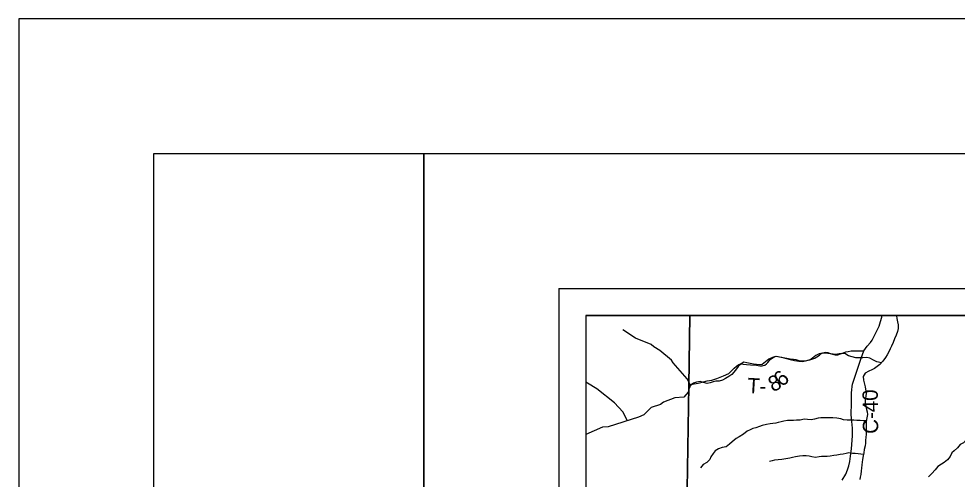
# Model space of a CAD drawing. Extents: x 0 to 34, y 0 to 22.
# Drawn here: x 0 to 3.475, y 20.293 to 22 of the extents above; entities that cross this region are included whole.
import ezdxf

# ---------------------------------------------------------------- set-up
doc = ezdxf.new("R2010")
doc.units = 0
for name, color, linetype in [('Default', 7, 'Continuous'), ('GM_X_County_Road', 7, 'Continuous'), ('GM_X_County_Road_Text', 7, 'Continuous'), ('GM_X_Minor_River', 7, 'Continuous'), ('GM_X_Township_Road', 7, 'Continuous'), ('GM_X_Township_Road_Text', 7, 'Continuous'), ('SH_Border', 7, 'Continuous'), ('SH_Cut_Line', 7, 'Continuous'), ('SH_Data', 7, 'Continuous')]:
    doc.layers.add(name, color=color, linetype=linetype)

msp = doc.modelspace()

# ---------------------------------------------------------------- linework, layer by layer
at = {"layer": 'Default'}
for points in [[(2.4313, 15.0183), (2.4545, 17.2795), (2.4586, 17.7785), (2.4581, 18.1772), (2.4581, 18.1825), (2.4573, 18.9074), (2.4757, 20.2566), (2.4809, 20.6393), (2.4845, 20.9), (2.1, 20.9), (2.1, 14.9328)], [(6.416, 20.9), (2.4845, 20.9), (2.4809, 20.6393), (2.4757, 20.2566), (2.4573, 18.9074), (2.4581, 18.1825), (2.4581, 18.1772), (2.4586, 17.7785), (2.4545, 17.2795), (2.6193, 17.2753), (3.4366, 17.255), (3.467, 17.2465), (3.4629, 17.4891), (3.5442, 17.5398)]]:
    msp.add_lwpolyline(points, dxfattribs=at)
at = {"layer": 'GM_X_County_Road'}
msp.add_lwpolyline([(3.0492, 20.2896), (3.0625, 20.3124), (3.0695, 20.3285), (3.0736, 20.3427), (3.0777, 20.3585), (3.0807, 20.3786), (3.0833, 20.4061), (3.0866, 20.4384), (3.0878, 20.4541), (3.0876, 20.4704), (3.0873, 20.4821), (3.0845, 20.507), (3.083, 20.5332), (3.0833, 20.5754), (3.0835, 20.6131), (3.0845, 20.625), (3.0858, 20.637), (3.0876, 20.6459), (3.0895, 20.6525), (3.1082, 20.7087), (3.1191, 20.742), (3.129, 20.7694), (3.1421, 20.7863), (3.1538, 20.8003), (3.1604, 20.8092), (3.1744, 20.8354), (3.1859, 20.8605), (3.1913, 20.8778), (3.1963, 20.8935), (3.1978, 20.9)], dxfattribs=at)
at = {"layer": 'GM_X_Minor_River'}
for points in [[(3.2506, 20.9), (3.2507, 20.8985), (3.2514, 20.8886), (3.2543, 20.8761), (3.2569, 20.8658), (3.2565, 20.8521), (3.2537, 20.8408), (3.2491, 20.8275), (3.2426, 20.8131), (3.2376, 20.8003), (3.2318, 20.787), (3.2272, 20.7768), (3.2222, 20.7658), (3.2161, 20.7549), (3.2092, 20.7451), (3.1996, 20.7311), (3.1882, 20.7182), (3.1786, 20.7107), (3.1691, 20.7036), (3.1596, 20.6987), (3.1475, 20.6935), (3.1342, 20.6859), (3.1265, 20.6742), (3.1279, 20.6606), (3.132, 20.6457), (3.1346, 20.6362), (3.1357, 20.6267), (3.1375, 20.6134), (3.137, 20.5994), (3.1339, 20.5861), (3.1342, 20.5744), (3.1364, 20.5649), (3.1394, 20.5523), (3.1416, 20.5428), (3.1427, 20.5333), (3.1407, 20.5204), (3.1376, 20.5076), (3.1383, 20.4943), (3.1378, 20.4833), (3.1377, 20.4586), (3.1372, 20.4487), (3.136, 20.437), (3.1352, 20.4268), (3.134, 20.4173), (3.1309, 20.404), (3.1293, 20.3911), (3.1269, 20.3805), (3.1246, 20.3669), (3.123, 20.357)], [(2.4871, 20.6422), (2.4747, 20.6655), (2.4232, 20.7244), (2.4174, 20.7348), (2.3744, 20.7703), (2.352, 20.7845), (2.3424, 20.7927), (2.2839, 20.8161), (2.237, 20.8465)], [(3.1943, 20.7251), (3.178, 20.7289), (3.1652, 20.7343), (3.1519, 20.742), (3.1402, 20.7447), (3.1262, 20.7433), (3.1, 20.7435), (3.0861, 20.747), (3.0724, 20.7505), (3.0585, 20.7589), (3.0475, 20.7597), (3.0376, 20.7575), (3.0247, 20.7561), (3.0077, 20.7577), (2.9963, 20.7593), (2.977, 20.7609), (2.9641, 20.7584), (2.952, 20.752), (2.939, 20.7422), (2.9291, 20.7351), (2.9181, 20.7317), (2.9056, 20.7303), (2.8931, 20.7304), (2.8787, 20.7361), (2.8685, 20.7377), (2.8568, 20.7389), (2.8443, 20.7413), (2.8291, 20.7429), (2.817, 20.746), (2.8038, 20.7484), (2.7913, 20.745), (2.778, 20.7379), (2.7654, 20.7281), (2.7525, 20.7187), (2.7418, 20.7173), (2.732, 20.7181), (2.7214, 20.7193), (2.7082, 20.7228), (2.6957, 20.7248), (2.6851, 20.7267), (2.6748, 20.7215), (2.6638, 20.7109), (2.6542, 20.6981), (2.6401, 20.6815), (2.6294, 20.6743), (2.6173, 20.6664), (2.6066, 20.6608), (2.5933, 20.6567), (2.582, 20.6568), (2.5721, 20.6546), (2.5599, 20.6512), (2.5497, 20.6483), (2.5361, 20.6522), (2.5236, 20.6553), (2.5099, 20.6531), (2.4986, 20.649), (2.4871, 20.6422), (2.4821, 20.6297), (2.4816, 20.6283)], [(2.2537, 20.5099), (2.2371, 20.543), (2.2066, 20.5771), (2.1401, 20.628), (2.1058, 20.6497), (2.1, 20.6528)], [(2.4816, 20.6283), (2.4793, 20.6161), (2.4624, 20.5971), (2.4294, 20.5953), (2.3874, 20.5784), (2.3766, 20.5707), (2.3423, 20.5587), (2.3152, 20.5324), (2.2956, 20.523), (2.1828, 20.4878), (2.1623, 20.486), (2.1, 20.4592)], [(3.1381, 20.5097), (3.127, 20.5103), (3.1164, 20.5115), (3.1031, 20.5116), (3.0925, 20.5124), (3.0819, 20.5125), (3.0683, 20.5118), (3.0547, 20.5134), (3.0444, 20.5169), (3.0289, 20.52), (3.0145, 20.5205), (2.9914, 20.5206), (2.9808, 20.5211), (2.9702, 20.5211), (2.9607, 20.5193), (2.9471, 20.516), (2.9345, 20.513), (2.9213, 20.5146), (2.9088, 20.5155), (2.894, 20.5125), (2.8804, 20.5122), (2.8694, 20.5112), (2.8466, 20.5113), (2.8337, 20.5091), (2.8239, 20.5058), (2.8125, 20.5032), (2.803, 20.5017), (2.7928, 20.5003), (2.7822, 20.4992), (2.7685, 20.4962), (2.7529, 20.4929), (2.7431, 20.4892), (2.729, 20.484), (2.718, 20.481), (2.7081, 20.4769), (2.6975, 20.4709), (2.6834, 20.4603), (2.6674, 20.4502), (2.6568, 20.4442), (2.6423, 20.4318), (2.6324, 20.4235), (2.6195, 20.4137), (2.6054, 20.4104), (2.5917, 20.4059), (2.5788, 20.3991), (2.5712, 20.3882), (2.5624, 20.3761), (2.5593, 20.3659), (2.5486, 20.3553), (2.5349, 20.3478), (2.5246, 20.335)], [(3.6901, 20.5082), (3.6805, 20.5131), (3.6687, 20.5101), (3.6588, 20.5018), (3.647, 20.4954), (3.6367, 20.497), (3.6258, 20.4982), (3.6098, 20.4942), (3.5977, 20.492), (3.584, 20.4898), (3.5711, 20.4857), (3.5601, 20.4823), (3.5502, 20.4809), (3.5399, 20.4764), (3.5285, 20.4635), (3.5166, 20.4503), (3.5097, 20.4401), (3.499, 20.428), (3.4868, 20.4224), (3.4765, 20.4092), (3.4634, 20.3985)], [(3.1279, 20.3847), (3.1179, 20.3863), (3.108, 20.3871), (3.0974, 20.389), (3.0872, 20.3891), (3.074, 20.3907), (3.0645, 20.3892), (3.0531, 20.3859), (3.0417, 20.3852), (3.0296, 20.383), (3.0178, 20.3808), (3.0046, 20.379), (2.9936, 20.3776), (2.983, 20.378), (2.9731, 20.3773), (2.9636, 20.3762), (2.95, 20.3737), (2.9367, 20.376), (2.9269, 20.3791), (2.9163, 20.3799), (2.9034, 20.38), (2.8913, 20.3786), (2.8769, 20.376), (2.8659, 20.3742), (2.8556, 20.372), (2.8404, 20.369), (2.8253, 20.3669), (2.812, 20.3654), (2.7991, 20.3636), (2.7896, 20.3621), (2.7798, 20.3592)], [(3.4634, 20.3985), (3.4555, 20.3909), (3.4486, 20.3777), (3.4394, 20.3649), (3.4269, 20.3558), (3.4173, 20.3494), (3.404, 20.34), (3.3937, 20.3276), (3.3815, 20.3144), (3.3693, 20.3019)], [(3.123, 20.357), (3.1218, 20.3468), (3.1206, 20.3342), (3.1194, 20.3244), (3.1186, 20.3111), (3.1162, 20.3016), (3.1146, 20.2922)]]:
    msp.add_lwpolyline(points, dxfattribs=at)
at = {"layer": 'GM_X_Township_Road'}
msp.add_lwpolyline([(2.4811, 20.6388), (2.4937, 20.6462), (2.5164, 20.649), (2.5313, 20.6528), (2.5496, 20.6575), (2.5665, 20.6605), (2.5855, 20.6661), (2.6101, 20.6762), (2.6295, 20.6846), (2.6492, 20.7045), (2.6578, 20.713), (2.6665, 20.7186), (2.673, 20.7216), (2.6822, 20.7198), (2.6944, 20.7184), (2.7096, 20.7172), (2.7321, 20.7165), (2.7447, 20.7141), (2.7529, 20.7138), (2.7571, 20.7146), (2.7627, 20.7162), (2.7686, 20.7212), (2.774, 20.7258), (2.7787, 20.7326), (2.784, 20.7385), (2.7934, 20.7446), (2.7993, 20.7488), (2.8072, 20.7495), (2.8168, 20.7474), (2.8248, 20.746), (2.8569, 20.7369), (2.8721, 20.7329), (2.889, 20.7303), (2.9028, 20.7301), (2.9133, 20.7317), (2.9274, 20.7354), (2.937, 20.7383), (2.9482, 20.7415), (2.9555, 20.7465), (2.9648, 20.7535), (2.9704, 20.7577), (2.9779, 20.7614), (2.988, 20.7645), (2.9957, 20.7626), (3.0049, 20.7598), (3.0138, 20.757), (3.0234, 20.7546), (3.033, 20.7546), (3.0428, 20.7577), (3.0538, 20.7612), (3.0622, 20.765), (3.0716, 20.7673), (3.0821, 20.7694), (3.0938, 20.7689), (3.106, 20.7694), (3.129, 20.7694)], dxfattribs=at)
at = {"layer": 'SH_Border'}
for points in [[(0.5, 21.5), (1.5, 21.5), (1.5, 0.5), (0.5, 0.5)], [(1.5, 21.5), (33.5, 21.5), (33.5, 0.5), (1.5, 0.5)]]:
    msp.add_lwpolyline(points, close=True, dxfattribs=at)
at = {"layer": 'SH_Cut_Line'}
for points in [[(0, 0), (34, 0), (34, 22), (0, 22)], [(2.4845, 20.9), (2.1, 20.9), (2.1, 14.1), (2.4352, 14.1), (2.4372, 14.2719), (2.4313, 15.0183), (2.4545, 17.2795), (2.4586, 17.7785), (2.4581, 18.1772), (2.4581, 18.1825), (2.4573, 18.9074), (2.4757, 20.2566), (2.4809, 20.6393)], [(2.4352, 14.1), (8.9, 14.1), (8.9, 20.9), (2.4845, 20.9), (2.4809, 20.6393), (2.4757, 20.2566), (2.4573, 18.9074), (2.4581, 18.1825), (2.4581, 18.1772), (2.4586, 17.7785), (2.4545, 17.2795), (2.4313, 15.0183), (2.4372, 14.2719)]]:
    msp.add_lwpolyline(points, close=True, dxfattribs=at)
at = {"layer": 'SH_Data'}
for p, q in [((2, 21), (9, 21)), ((2, 21), (2, 14)), ((2.1, 20.9), (2.1, 14.1)), ((2.1, 20.9), (8.9, 20.9))]:
    msp.add_line(p, q, dxfattribs=at)

# ---------------------------------------------------------------- texts
at = {"layer": 'GM_X_County_Road_Text'}
msp.add_text('C-40', height=0.05682, rotation=90.6751, dxfattribs=at).set_placement((3.1829, 20.4618))
at = {"layer": 'GM_X_Township_Road_Text'}
for s, rotation, p in [('8', 24.6511, (2.7916, 20.6155)), ('6', 43.493, (2.8275, 20.6329)), ('T', 356.548, (2.6963, 20.6127)), ('-', 359.6434, (2.7421, 20.61))]:
    msp.add_text(s, height=0.0568, rotation=rotation, dxfattribs=at).set_placement(p)

doc.saveas('drawing.dxf')
